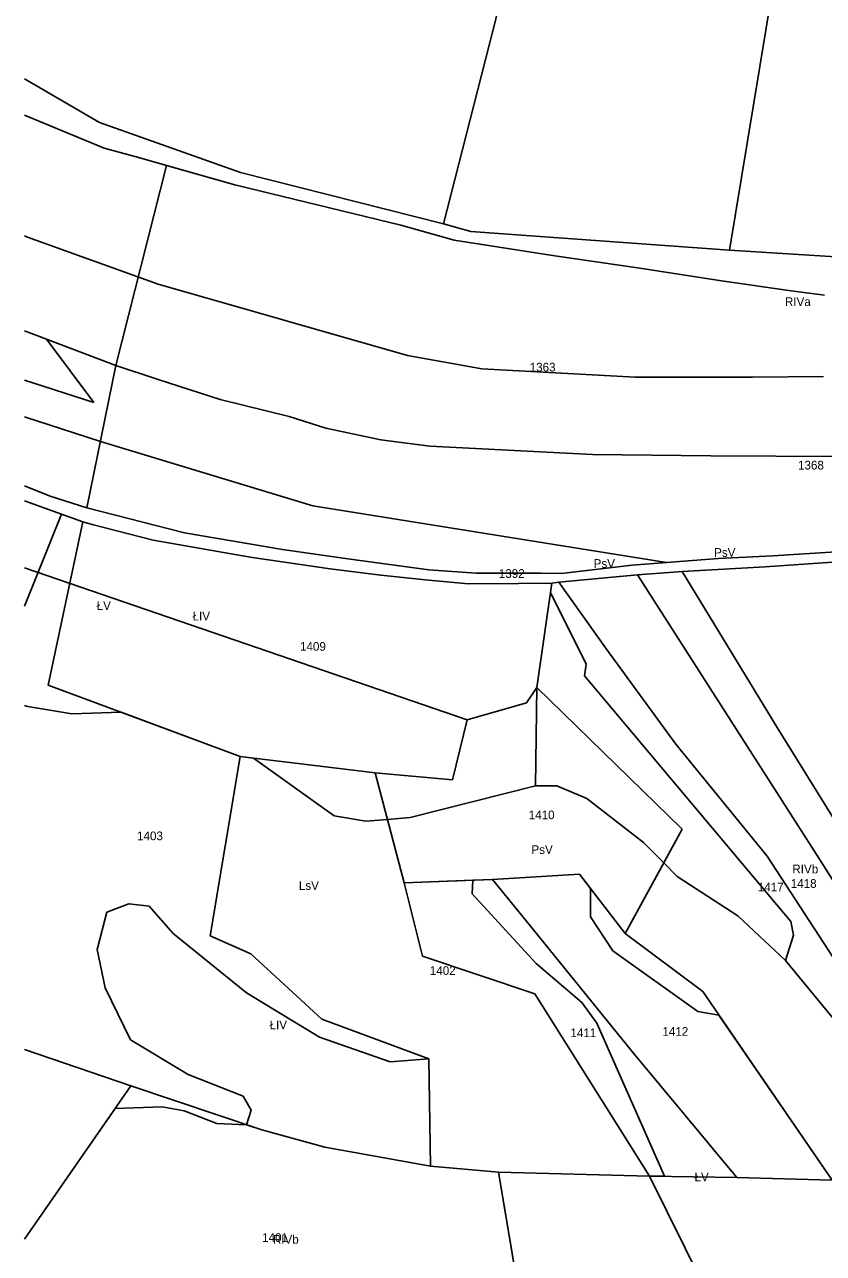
# Model space of a CAD drawing. Extents: x 7498273 to 7499989, y 5499795 to 5500810.
# Drawn here: x 7498273.2 to 7498411, y 5499981.5 to 5500193.5 of the extents above; entities that cross this region are included whole.
import ezdxf

# ---------------------------------------------------------------- set-up
doc = ezdxf.new("R2010")
doc.units = 0
for name, color, linetype in [('209-oznaczenie konturu klasyfikacyjnego', 7, 'Continuous'), ('211-numer działki ewidencyjnej', 7, 'Continuous'), ('217-kontur klasyfikacyjny', 7, 'Continuous'), ('218-kontur użytku gruntowego', 7, 'Continuous'), ('219-działka ewidencyjna', 7, 'Continuous')]:
    doc.layers.add(name, color=color, linetype=linetype)

msp = doc.modelspace()

# ---------------------------------------------------------------- linework, layer by layer
at = {"layer": '217-kontur klasyfikacyjny'}
for points in [[(7498273.174, 5500184.16), (7498286.09, 5500176.63)], [(7498286.88, 5500172.18), (7498273.174, 5500177.907)], [(7498286.09, 5500176.63), (7498310.45, 5500168.02)], [(7498292.4, 5500170.68), (7498286.88, 5500172.18)], [(7498297.68, 5500169.19), (7498292.4, 5500170.68)], [(7498288.94, 5500134.72), (7498297.68, 5500169.19)], [(7498309.44, 5500165.87), (7498297.68, 5500169.19)], [(7498310.45, 5500168.02), (7498345.48, 5500159.15)], [(7498338.1, 5500158.91), (7498309.44, 5500165.87)], [(7498347.29, 5500156.34), (7498338.1, 5500158.91)], [(7498345.48, 5500159.15), (7498350.18, 5500157.84)], [(7498350.18, 5500157.84), (7498394.78, 5500154.57)], [(7498364.68, 5500153.6), (7498347.29, 5500156.34)], [(7498379.31, 5500151.51), (7498364.68, 5500153.6)], [(7498394.78, 5500154.57), (7498418.64, 5500153.08)], [(7498393.4, 5500149.33), (7498379.31, 5500151.51)], [(7498405.44, 5500147.57), (7498393.4, 5500149.33)], [(7498411.19, 5500146.84), (7498405.44, 5500147.57)], [(7498276.97, 5500139.22), (7498273.174, 5500140.648)], [(7498288.94, 5500134.72), (7498276.97, 5500139.22)], [(7498276.97, 5500139.22), (7498285.14, 5500128.29)], [(7498296.2, 5500132.26), (7498288.94, 5500134.72)], [(7498285.14, 5500128.29), (7498273.174, 5500132.172)], [(7498306.92, 5500128.81), (7498296.2, 5500132.26)], [(7498318.85, 5500125.91), (7498306.92, 5500128.81)], [(7498273.174, 5500125.821), (7498286.25, 5500121.61)], [(7498325.16, 5500123.88), (7498318.85, 5500125.91)], [(7498334.66, 5500121.86), (7498325.16, 5500123.88)], [(7498343.1, 5500120.8), (7498334.66, 5500121.86)], [(7498286.25, 5500121.61), (7498322.89, 5500110.51)], [(7498371.15, 5500119.31), (7498343.1, 5500120.8)], [(7498391.61, 5500119.08), (7498371.15, 5500119.31)], [(7498425.24, 5500118.92), (7498391.61, 5500119.08)], [(7498273.174, 5500113.952), (7498277.6, 5500112.17)], [(7498279.53, 5500109.02), (7498273.174, 5500111.352)], [(7498277.6, 5500112.17), (7498283.89, 5500110.13)], [(7498283.89, 5500110.13), (7498300.75, 5500105.83)], [(7498322.89, 5500110.51), (7498383.92, 5500100.68)], [(7498283.2, 5500107.73), (7498279.53, 5500109.02)], [(7498284.83, 5500107.26), (7498283.2, 5500107.73)], [(7498295.34, 5500104.58), (7498284.83, 5500107.26)], [(7498300.75, 5500105.83), (7498317.65, 5500102.93)], [(7498312.12, 5500101.62), (7498295.34, 5500104.58)], [(7498317.65, 5500102.93), (7498328.96, 5500101.31)], [(7498402.27, 5500101.87), (7498417.77, 5500102.84)], [(7498325.93, 5500099.59), (7498312.12, 5500101.62)], [(7498328.96, 5500101.31), (7498342.95, 5500099.43)], [(7498378.04, 5500100.22), (7498383.92, 5500100.68)], [(7498383.92, 5500100.68), (7498392.92, 5500101.38)], [(7498392.92, 5500101.38), (7498402.27, 5500101.87)], [(7498415.93, 5500100.97), (7498400.97, 5500099.94)], [(7498273.174, 5500099.787), (7498349.56, 5500073.54)], [(7498334.67, 5500098.53), (7498325.93, 5500099.59)], [(7498342.86, 5500097.65), (7498334.67, 5500098.53)], [(7498342.95, 5500099.43), (7498351.01, 5500098.89)], [(7498351.01, 5500098.89), (7498362.33, 5500098.85)], [(7498362.33, 5500098.85), (7498365.78, 5500098.78)], [(7498378.95, 5500098.57), (7498365.35, 5500097.33)], [(7498365.78, 5500098.78), (7498378.04, 5500100.22)], [(7498386.63, 5500099.18), (7498378.95, 5500098.57)], [(7498410.35, 5500049.5), (7498378.95, 5500098.57)], [(7498400.97, 5500099.94), (7498386.63, 5500099.18)], [(7498349.76, 5500097.05), (7498342.86, 5500097.65)], [(7498358.42, 5500097.06), (7498349.76, 5500097.05)], [(7498364.15, 5500097.12), (7498358.42, 5500097.06)], [(7498363.92, 5500095.53), (7498364.15, 5500097.12)], [(7498365.35, 5500097.33), (7498364.15, 5500097.12)], [(7498370.1, 5500083.15), (7498363.92, 5500095.53)], [(7498369.8, 5500081.16), (7498370.1, 5500083.15)], [(7498405.39, 5500038.77), (7498369.8, 5500081.16)], [(7498359.78, 5500076.52), (7498361.56, 5500079.12)], [(7498361.56, 5500079.12), (7498361.36, 5500062.15)], [(7498273.74, 5500075.86), (7498273.174, 5500076.057)], [(7498281.35, 5500074.62), (7498273.74, 5500075.86)], [(7498349.56, 5500073.54), (7498359.78, 5500076.52)], [(7498289.85, 5500074.86), (7498281.35, 5500074.62)], [(7498310.36, 5500067.25), (7498289.85, 5500074.86)], [(7498312.66, 5500066.97), (7498310.36, 5500067.25)], [(7498326.6, 5500057.02), (7498312.66, 5500066.97)], [(7498339.7, 5500056.69), (7498361.36, 5500062.15)], [(7498361.36, 5500062.15), (7498365.01, 5500062.16)], [(7498365.01, 5500062.16), (7498370.18, 5500059.96)], [(7498370.18, 5500059.96), (7498379.99, 5500052.4)], [(7498332.05, 5500056.05), (7498326.6, 5500057.02)], [(7498335.78, 5500056.36), (7498332.05, 5500056.05)], [(7498335.78, 5500056.36), (7498339.7, 5500056.69)], [(7498338.66, 5500045.42), (7498335.78, 5500056.36)], [(7498379.99, 5500052.4), (7498383.48, 5500048.87)], [(7498376.81, 5500036.68), (7498383.48, 5500048.87)], [(7498383.48, 5500048.87), (7498385.8, 5500046.53)], [(7498431.73, 5500015.7), (7498410.35, 5500049.5)], [(7498350.54, 5500045.87), (7498338.66, 5500045.42)], [(7498350.41, 5500043.54), (7498350.54, 5500045.87)], [(7498350.54, 5500045.87), (7498353.93, 5500046)], [(7498353.93, 5500046), (7498368.92, 5500046.93)], [(7498368.92, 5500046.93), (7498370.84, 5500044.43)], [(7498385.8, 5500046.53), (7498396.23, 5500039.76)], [(7498361.42, 5500031.5), (7498350.41, 5500043.54)], [(7498370.83, 5500039.56), (7498370.84, 5500044.43)], [(7498370.84, 5500044.43), (7498376.81, 5500036.68)], [(7498287.35, 5500040.36), (7498291.14, 5500041.81)], [(7498291.14, 5500041.81), (7498294.66, 5500041.4)], [(7498294.66, 5500041.4), (7498298.8, 5500036.71)], [(7498285.69, 5500033.95), (7498287.35, 5500040.36)], [(7498374.69, 5500033.71), (7498370.83, 5500039.56)], [(7498396.23, 5500039.76), (7498404.49, 5500032.01)], [(7498405.87, 5500036.43), (7498405.39, 5500038.77)], [(7498298.8, 5500036.71), (7498311.49, 5500026.43)], [(7498404.49, 5500032.01), (7498405.87, 5500036.43)], [(7498287.07, 5500027.32), (7498285.69, 5500033.95)], [(7498389.37, 5500023.24), (7498374.69, 5500033.71)], [(7498369.35, 5500024.81), (7498361.42, 5500031.5)], [(7498404.49, 5500032.01), (7498421.39, 5500011.53)], [(7498291.45, 5500018.35), (7498287.07, 5500027.32)], [(7498311.49, 5500026.43), (7498324.07, 5500018.81)], [(7498371.93, 5500021.23), (7498369.35, 5500024.81)], [(7498392.97, 5500022.63), (7498389.37, 5500023.24)], [(7498412.52, 5499994.14), (7498392.97, 5500022.63)], [(7498383.57, 5499994.8), (7498371.93, 5500021.23)], [(7498301.38, 5500012.35), (7498291.45, 5500018.35)], [(7498324.07, 5500018.81), (7498336.26, 5500014.54)], [(7498336.26, 5500014.54), (7498342.92, 5500015.07)], [(7498342.92, 5500015.07), (7498343.21, 5499996.55)], [(7498310.9, 5500008.62), (7498301.38, 5500012.35)], [(7498312.28, 5500006.21), (7498310.9, 5500008.62)], [(7498273.174, 5499983.956), (7498288.8, 5500006.51)], [(7498288.8, 5500006.51), (7498296.9, 5500006.76)], [(7498296.9, 5500006.76), (7498300.69, 5500006.07)], [(7498300.69, 5500006.07), (7498306.35, 5500003.93)], [(7498311.45, 5500003.7), (7498312.28, 5500006.21)], [(7498306.35, 5500003.93), (7498311.45, 5500003.7)], [(7498314.13, 5500002.8), (7498311.45, 5500003.7)], [(7498324.99, 5499999.8), (7498314.13, 5500002.8)], [(7498343.21, 5499996.55), (7498324.99, 5499999.8)], [(7498343.21, 5499996.55), (7498354.96, 5499995.54)], [(7498354.96, 5499995.54), (7498360.15, 5499964.66)], [(7498408.66, 5499938.97), (7498380.98, 5499994.84)], [(7498380.98, 5499994.84), (7498383.57, 5499994.8)]]:
    msp.add_lwpolyline(points, dxfattribs=at)
at = {"layer": '218-kontur użytku gruntowego'}
for points in [[(7498273.174, 5500184.16), (7498286.09, 5500176.63)], [(7498286.88, 5500172.18), (7498273.174, 5500177.907)], [(7498286.09, 5500176.63), (7498310.45, 5500168.02)], [(7498292.4, 5500170.68), (7498286.88, 5500172.18)], [(7498297.68, 5500169.19), (7498292.4, 5500170.68)], [(7498297.68, 5500169.19), (7498288.94, 5500134.72)], [(7498309.44, 5500165.87), (7498297.68, 5500169.19)], [(7498310.45, 5500168.02), (7498345.48, 5500159.15)], [(7498338.1, 5500158.91), (7498309.44, 5500165.87)], [(7498347.29, 5500156.34), (7498338.1, 5500158.91)], [(7498345.48, 5500159.15), (7498350.18, 5500157.84)], [(7498350.18, 5500157.84), (7498394.78, 5500154.57)], [(7498364.68, 5500153.6), (7498347.29, 5500156.34)], [(7498379.31, 5500151.51), (7498364.68, 5500153.6)], [(7498394.78, 5500154.57), (7498418.64, 5500153.08)], [(7498393.4, 5500149.33), (7498379.31, 5500151.51)], [(7498405.44, 5500147.57), (7498393.4, 5500149.33)], [(7498411.19, 5500146.84), (7498405.44, 5500147.57)], [(7498273.174, 5500140.648), (7498276.97, 5500139.22)], [(7498276.97, 5500139.22), (7498288.94, 5500134.72)], [(7498276.97, 5500139.22), (7498285.14, 5500128.29)], [(7498288.94, 5500134.72), (7498296.2, 5500132.26)], [(7498285.14, 5500128.29), (7498273.174, 5500132.172)], [(7498296.2, 5500132.26), (7498306.92, 5500128.81)], [(7498306.92, 5500128.81), (7498318.85, 5500125.91)], [(7498286.25, 5500121.61), (7498273.174, 5500125.821)], [(7498318.85, 5500125.91), (7498325.16, 5500123.88)], [(7498325.16, 5500123.88), (7498334.66, 5500121.86)], [(7498334.66, 5500121.86), (7498343.1, 5500120.8)], [(7498322.89, 5500110.51), (7498286.25, 5500121.61)], [(7498343.1, 5500120.8), (7498371.15, 5500119.31)], [(7498371.15, 5500119.31), (7498391.61, 5500119.08)], [(7498391.61, 5500119.08), (7498425.24, 5500118.92)], [(7498273.174, 5500113.952), (7498277.6, 5500112.17)], [(7498279.53, 5500109.02), (7498273.174, 5500111.352)], [(7498277.6, 5500112.17), (7498283.89, 5500110.13)], [(7498283.89, 5500110.13), (7498300.75, 5500105.83)], [(7498383.92, 5500100.68), (7498322.89, 5500110.51)], [(7498283.2, 5500107.73), (7498279.53, 5500109.02)], [(7498284.83, 5500107.26), (7498283.2, 5500107.73)], [(7498295.34, 5500104.58), (7498284.83, 5500107.26)], [(7498300.75, 5500105.83), (7498317.65, 5500102.93)], [(7498312.12, 5500101.62), (7498295.34, 5500104.58)], [(7498317.65, 5500102.93), (7498328.96, 5500101.31)], [(7498402.27, 5500101.87), (7498417.77, 5500102.84)], [(7498325.93, 5500099.59), (7498312.12, 5500101.62)], [(7498328.96, 5500101.31), (7498342.95, 5500099.43)], [(7498378.04, 5500100.22), (7498383.92, 5500100.68)], [(7498383.92, 5500100.68), (7498392.92, 5500101.38)], [(7498392.92, 5500101.38), (7498402.27, 5500101.87)], [(7498415.93, 5500100.97), (7498400.97, 5500099.94)], [(7498273.174, 5500099.787), (7498349.56, 5500073.54)], [(7498334.67, 5500098.53), (7498325.93, 5500099.59)], [(7498342.86, 5500097.65), (7498334.67, 5500098.53)], [(7498342.95, 5500099.43), (7498351.01, 5500098.89)], [(7498351.01, 5500098.89), (7498362.33, 5500098.85)], [(7498362.33, 5500098.85), (7498365.78, 5500098.78)], [(7498378.95, 5500098.57), (7498365.35, 5500097.33)], [(7498365.78, 5500098.78), (7498378.04, 5500100.22)], [(7498386.63, 5500099.18), (7498378.95, 5500098.57)], [(7498378.95, 5500098.57), (7498410.35, 5500049.5)], [(7498400.97, 5500099.94), (7498386.63, 5500099.18)], [(7498349.76, 5500097.05), (7498342.86, 5500097.65)], [(7498358.42, 5500097.06), (7498349.76, 5500097.05)], [(7498364.15, 5500097.12), (7498358.42, 5500097.06)], [(7498364.15, 5500097.12), (7498363.92, 5500095.53)], [(7498365.35, 5500097.33), (7498364.15, 5500097.12)], [(7498363.92, 5500095.53), (7498370.1, 5500083.15)], [(7498370.1, 5500083.15), (7498369.8, 5500081.16)], [(7498369.8, 5500081.16), (7498405.39, 5500038.77)], [(7498359.78, 5500076.52), (7498361.56, 5500079.12)], [(7498361.56, 5500079.12), (7498361.36, 5500062.15)], [(7498273.74, 5500075.86), (7498273.174, 5500076.057)], [(7498281.35, 5500074.62), (7498273.74, 5500075.86)], [(7498349.56, 5500073.54), (7498359.78, 5500076.52)], [(7498289.85, 5500074.86), (7498281.35, 5500074.62)], [(7498310.36, 5500067.25), (7498289.85, 5500074.86)], [(7498312.66, 5500066.97), (7498310.36, 5500067.25)], [(7498326.6, 5500057.02), (7498312.66, 5500066.97)], [(7498361.36, 5500062.15), (7498339.7, 5500056.69)], [(7498365.01, 5500062.16), (7498361.36, 5500062.15)], [(7498370.18, 5500059.96), (7498365.01, 5500062.16)], [(7498379.99, 5500052.4), (7498370.18, 5500059.96)], [(7498332.05, 5500056.05), (7498326.6, 5500057.02)], [(7498335.78, 5500056.36), (7498332.05, 5500056.05)], [(7498339.7, 5500056.69), (7498335.78, 5500056.36)], [(7498335.78, 5500056.36), (7498338.66, 5500045.42)], [(7498383.48, 5500048.87), (7498379.99, 5500052.4)], [(7498383.48, 5500048.87), (7498376.81, 5500036.68)], [(7498385.8, 5500046.53), (7498383.48, 5500048.87)], [(7498410.35, 5500049.5), (7498431.73, 5500015.7)], [(7498338.66, 5500045.42), (7498350.54, 5500045.87)], [(7498350.54, 5500045.87), (7498350.41, 5500043.54)], [(7498350.54, 5500045.87), (7498353.93, 5500046)], [(7498353.93, 5500046), (7498368.92, 5500046.93)], [(7498368.92, 5500046.93), (7498370.84, 5500044.43)], [(7498396.23, 5500039.76), (7498385.8, 5500046.53)], [(7498350.41, 5500043.54), (7498361.42, 5500031.5)], [(7498370.84, 5500044.43), (7498370.83, 5500039.56)], [(7498376.81, 5500036.68), (7498370.84, 5500044.43)], [(7498291.14, 5500041.81), (7498287.35, 5500040.36)], [(7498294.66, 5500041.4), (7498291.14, 5500041.81)], [(7498298.8, 5500036.71), (7498294.66, 5500041.4)], [(7498287.35, 5500040.36), (7498285.69, 5500033.95)], [(7498370.83, 5500039.56), (7498374.69, 5500033.71)], [(7498404.49, 5500032.01), (7498396.23, 5500039.76)], [(7498405.39, 5500038.77), (7498405.87, 5500036.43)], [(7498311.49, 5500026.43), (7498298.8, 5500036.71)], [(7498405.87, 5500036.43), (7498404.49, 5500032.01)], [(7498285.69, 5500033.95), (7498287.07, 5500027.32)], [(7498374.69, 5500033.71), (7498389.37, 5500023.24)], [(7498361.42, 5500031.5), (7498369.35, 5500024.81)], [(7498404.49, 5500032.01), (7498421.39, 5500011.53)], [(7498287.07, 5500027.32), (7498291.45, 5500018.35)], [(7498324.07, 5500018.81), (7498311.49, 5500026.43)], [(7498369.35, 5500024.81), (7498371.93, 5500021.23)], [(7498389.37, 5500023.24), (7498392.97, 5500022.63)], [(7498392.97, 5500022.63), (7498412.52, 5499994.14)], [(7498371.93, 5500021.23), (7498383.57, 5499994.8)], [(7498291.45, 5500018.35), (7498301.38, 5500012.35)], [(7498336.26, 5500014.54), (7498324.07, 5500018.81)], [(7498342.92, 5500015.07), (7498336.26, 5500014.54)], [(7498343.21, 5499996.55), (7498342.92, 5500015.07)], [(7498301.38, 5500012.35), (7498310.9, 5500008.62)], [(7498310.9, 5500008.62), (7498312.28, 5500006.21)], [(7498288.8, 5500006.51), (7498273.174, 5499983.956)], [(7498296.9, 5500006.76), (7498288.8, 5500006.51)], [(7498300.69, 5500006.07), (7498296.9, 5500006.76)], [(7498306.35, 5500003.93), (7498300.69, 5500006.07)], [(7498312.28, 5500006.21), (7498311.45, 5500003.7)], [(7498311.45, 5500003.7), (7498306.35, 5500003.93)], [(7498311.45, 5500003.7), (7498314.13, 5500002.8)], [(7498314.13, 5500002.8), (7498324.99, 5499999.8)], [(7498324.99, 5499999.8), (7498343.21, 5499996.55)], [(7498354.96, 5499995.54), (7498343.21, 5499996.55)], [(7498360.15, 5499964.66), (7498354.96, 5499995.54)], [(7498383.57, 5499994.8), (7498380.98, 5499994.84)], [(7498380.98, 5499994.84), (7498408.66, 5499938.97)]]:
    msp.add_lwpolyline(points, dxfattribs=at)
at = {"layer": '219-działka ewidencyjna'}
for points in [[(7498394.78, 5500154.57), (7498409.43, 5500243.11)], [(7498345.48, 5500159.15), (7498361.22, 5500220.85)], [(7498273.174, 5500184.16), (7498286.09, 5500176.63)], [(7498273.174, 5500177.907), (7498286.88, 5500172.18)], [(7498310.45, 5500168.02), (7498286.09, 5500176.63)], [(7498286.88, 5500172.18), (7498292.4, 5500170.68)], [(7498292.4, 5500170.68), (7498309.44, 5500165.87)], [(7498310.45, 5500168.02), (7498345.48, 5500159.15)], [(7498309.44, 5500165.87), (7498338.1, 5500158.91)], [(7498338.1, 5500158.91), (7498347.29, 5500156.34)], [(7498350.18, 5500157.84), (7498345.48, 5500159.15)], [(7498350.18, 5500157.84), (7498394.78, 5500154.57)], [(7498273.174, 5500157.042), (7498273.67, 5500156.86)], [(7498273.67, 5500156.86), (7498296.21, 5500148.72)], [(7498347.29, 5500156.34), (7498364.68, 5500153.6)], [(7498364.68, 5500153.6), (7498379.31, 5500151.51)], [(7498394.78, 5500154.57), (7498418.64, 5500153.08)], [(7498379.31, 5500151.51), (7498393.4, 5500149.33)], [(7498405.44, 5500147.57), (7498393.4, 5500149.33)], [(7498339.26, 5500136.44), (7498296.21, 5500148.72)], [(7498405.44, 5500147.57), (7498411.19, 5500146.84)], [(7498273.174, 5500140.649), (7498288.94, 5500134.72)], [(7498283.89, 5500110.13), (7498288.94, 5500134.72)], [(7498288.94, 5500134.72), (7498296.2, 5500132.26)], [(7498339.26, 5500136.44), (7498352.07, 5500134.1)], [(7498352.07, 5500134.1), (7498378.54, 5500132.66)], [(7498398.79, 5500132.7), (7498378.54, 5500132.66)], [(7498398.79, 5500132.7), (7498411.02, 5500132.82)], [(7498306.92, 5500128.81), (7498296.2, 5500132.26)], [(7498306.92, 5500128.81), (7498318.85, 5500125.91)], [(7498318.85, 5500125.91), (7498325.16, 5500123.88)], [(7498325.16, 5500123.88), (7498334.66, 5500121.86)], [(7498343.1, 5500120.8), (7498334.66, 5500121.86)], [(7498343.1, 5500120.8), (7498371.15, 5500119.31)], [(7498371.15, 5500119.31), (7498391.61, 5500119.08)], [(7498391.61, 5500119.08), (7498425.24, 5500118.92)], [(7498277.6, 5500112.17), (7498273.174, 5500113.952)], [(7498273.174, 5500111.352), (7498279.53, 5500109.02)], [(7498277.6, 5500112.17), (7498283.89, 5500110.13)], [(7498300.75, 5500105.83), (7498283.89, 5500110.13)], [(7498273.174, 5500093.197), (7498279.53, 5500109.02)], [(7498283.2, 5500107.73), (7498277.24, 5500079.53)], [(7498283.2, 5500107.73), (7498279.53, 5500109.02)], [(7498283.2, 5500107.73), (7498284.83, 5500107.26)], [(7498284.83, 5500107.26), (7498295.34, 5500104.58)], [(7498300.75, 5500105.83), (7498317.65, 5500102.93)], [(7498295.34, 5500104.58), (7498312.12, 5500101.62)], [(7498317.65, 5500102.93), (7498328.96, 5500101.31)], [(7498402.27, 5500101.87), (7498417.77, 5500102.84)], [(7498312.12, 5500101.62), (7498325.93, 5500099.59)], [(7498328.96, 5500101.31), (7498342.95, 5500099.43)], [(7498378.04, 5500100.22), (7498392.92, 5500101.38)], [(7498392.92, 5500101.38), (7498402.27, 5500101.87)], [(7498400.97, 5500099.94), (7498415.93, 5500100.97)], [(7498325.93, 5500099.59), (7498334.67, 5500098.53)], [(7498342.86, 5500097.65), (7498334.67, 5500098.53)], [(7498342.95, 5500099.43), (7498351.01, 5500098.89)], [(7498351.01, 5500098.89), (7498362.33, 5500098.85)], [(7498362.33, 5500098.85), (7498365.78, 5500098.78)], [(7498365.35, 5500097.33), (7498378.95, 5500098.57)], [(7498365.78, 5500098.78), (7498378.04, 5500100.22)], [(7498378.95, 5500098.57), (7498386.63, 5500099.18)], [(7498378.95, 5500098.57), (7498410.35, 5500049.5)], [(7498386.63, 5500099.18), (7498400.97, 5500099.94)], [(7498386.63, 5500099.18), (7498403.02, 5500072.21)], [(7498342.86, 5500097.65), (7498349.76, 5500097.05)], [(7498349.76, 5500097.05), (7498358.42, 5500097.06)], [(7498358.42, 5500097.06), (7498364.15, 5500097.12)], [(7498361.56, 5500079.12), (7498364.15, 5500097.12)], [(7498364.15, 5500097.12), (7498365.35, 5500097.33)], [(7498365.35, 5500097.33), (7498373.61, 5500085.75)], [(7498373.61, 5500085.75), (7498385.52, 5500069.34)], [(7498277.24, 5500079.53), (7498310.36, 5500067.25)], [(7498359.78, 5500076.52), (7498361.56, 5500079.12)], [(7498361.56, 5500079.12), (7498386.65, 5500054.67)], [(7498349.56, 5500073.54), (7498359.78, 5500076.52)], [(7498347.01, 5500063.22), (7498349.56, 5500073.54)], [(7498403.02, 5500072.21), (7498427.53, 5500032.71)], [(7498385.52, 5500069.34), (7498401.31, 5500050.04)], [(7498305.22, 5500036.28), (7498310.36, 5500067.25)], [(7498310.36, 5500067.25), (7498333.66, 5500064.42)], [(7498333.66, 5500064.42), (7498338.66, 5500045.42)], [(7498333.66, 5500064.42), (7498347.01, 5500063.22)], [(7498376.81, 5500036.68), (7498386.65, 5500054.67)], [(7498401.31, 5500050.04), (7498420.84, 5500019.99)], [(7498410.35, 5500049.5), (7498431.73, 5500015.7)], [(7498338.66, 5500045.42), (7498353.93, 5500046)], [(7498338.66, 5500045.42), (7498341.85, 5500032.8)], [(7498353.93, 5500046), (7498368.92, 5500046.93)], [(7498360.99, 5500037.3), (7498353.93, 5500046)], [(7498368.92, 5500046.93), (7498376.81, 5500036.68)], [(7498360.99, 5500037.3), (7498378.17, 5500016.11)], [(7498305.22, 5500036.28), (7498312.24, 5500033.21)], [(7498376.81, 5500036.68), (7498390.2, 5500026.66)], [(7498312.24, 5500033.21), (7498324.45, 5500021.92)], [(7498341.85, 5500032.8), (7498361.23, 5500026.3)], [(7498390.2, 5500026.66), (7498412.52, 5499994.14)], [(7498361.23, 5500026.3), (7498380.98, 5499994.84)], [(7498324.45, 5500021.92), (7498342.92, 5500015.07)], [(7498273.174, 5500016.679), (7498291.5, 5500010.4)], [(7498378.17, 5500016.11), (7498396.06, 5499994.62)], [(7498342.92, 5500015.07), (7498343.21, 5499996.55)], [(7498273.174, 5499983.965), (7498291.5, 5500010.4)], [(7498291.5, 5500010.4), (7498314.13, 5500002.8)], [(7498314.13, 5500002.8), (7498324.99, 5499999.8)], [(7498324.99, 5499999.8), (7498343.21, 5499996.55)], [(7498343.21, 5499996.55), (7498354.96, 5499995.54)], [(7498354.96, 5499995.54), (7498361.51, 5499956.56)], [(7498354.96, 5499995.54), (7498380.98, 5499994.84)], [(7498380.98, 5499994.84), (7498396.06, 5499994.62)], [(7498380.98, 5499994.84), (7498408.66, 5499938.97)], [(7498396.06, 5499994.62), (7498412.52, 5499994.14)]]:
    msp.add_lwpolyline(points, dxfattribs=at)

# ---------------------------------------------------------------- texts
at = {"layer": '209-oznaczenie konturu klasyfikacyjnego'}
for s, p in [('RIVa', (7498404.37, 5500144.96)), ('PsV', (7498392.15, 5500101.68)), ('PsV', (7498371.36, 5500099.78)), ('ŁV', (7498285.61, 5500092.52)), ('ŁIV', (7498302.16, 5500090.7)), ('PsV', (7498360.63, 5500050.42)), ('RIVb', (7498405.65, 5500047.07)), ('LsV', (7498320.5, 5500044.22)), ('ŁIV', (7498315.45, 5500020.18)), ('ŁV', (7498388.77, 5499993.95)), ('RIVb', (7498316.02, 5499983.17))]:
    msp.add_text(s, height=1.5, dxfattribs=at).set_placement(p)
at = {"layer": '211-numer działki ewidencyjnej'}
for s, p in [('1363', (7498360.33, 5500133.66)), ('1368', (7498406.63, 5500116.75)), ('1392', (7498355, 5500098.05)), ('1409', (7498320.7, 5500085.48)), ('1410', (7498360.16, 5500056.4)), ('1403', (7498292.58, 5500052.79)), ('1417', (7498399.68, 5500043.95)), ('1418', (7498405.37, 5500044.57)), ('1402', (7498343.1, 5500029.55)), ('1411', (7498367.36, 5500018.81)), ('1412', (7498383.23, 5500019.04)), ('1401', (7498314.16, 5499983.48))]:
    msp.add_text(s, height=1.5, dxfattribs=at).set_placement(p)

doc.saveas('drawing.dxf')
